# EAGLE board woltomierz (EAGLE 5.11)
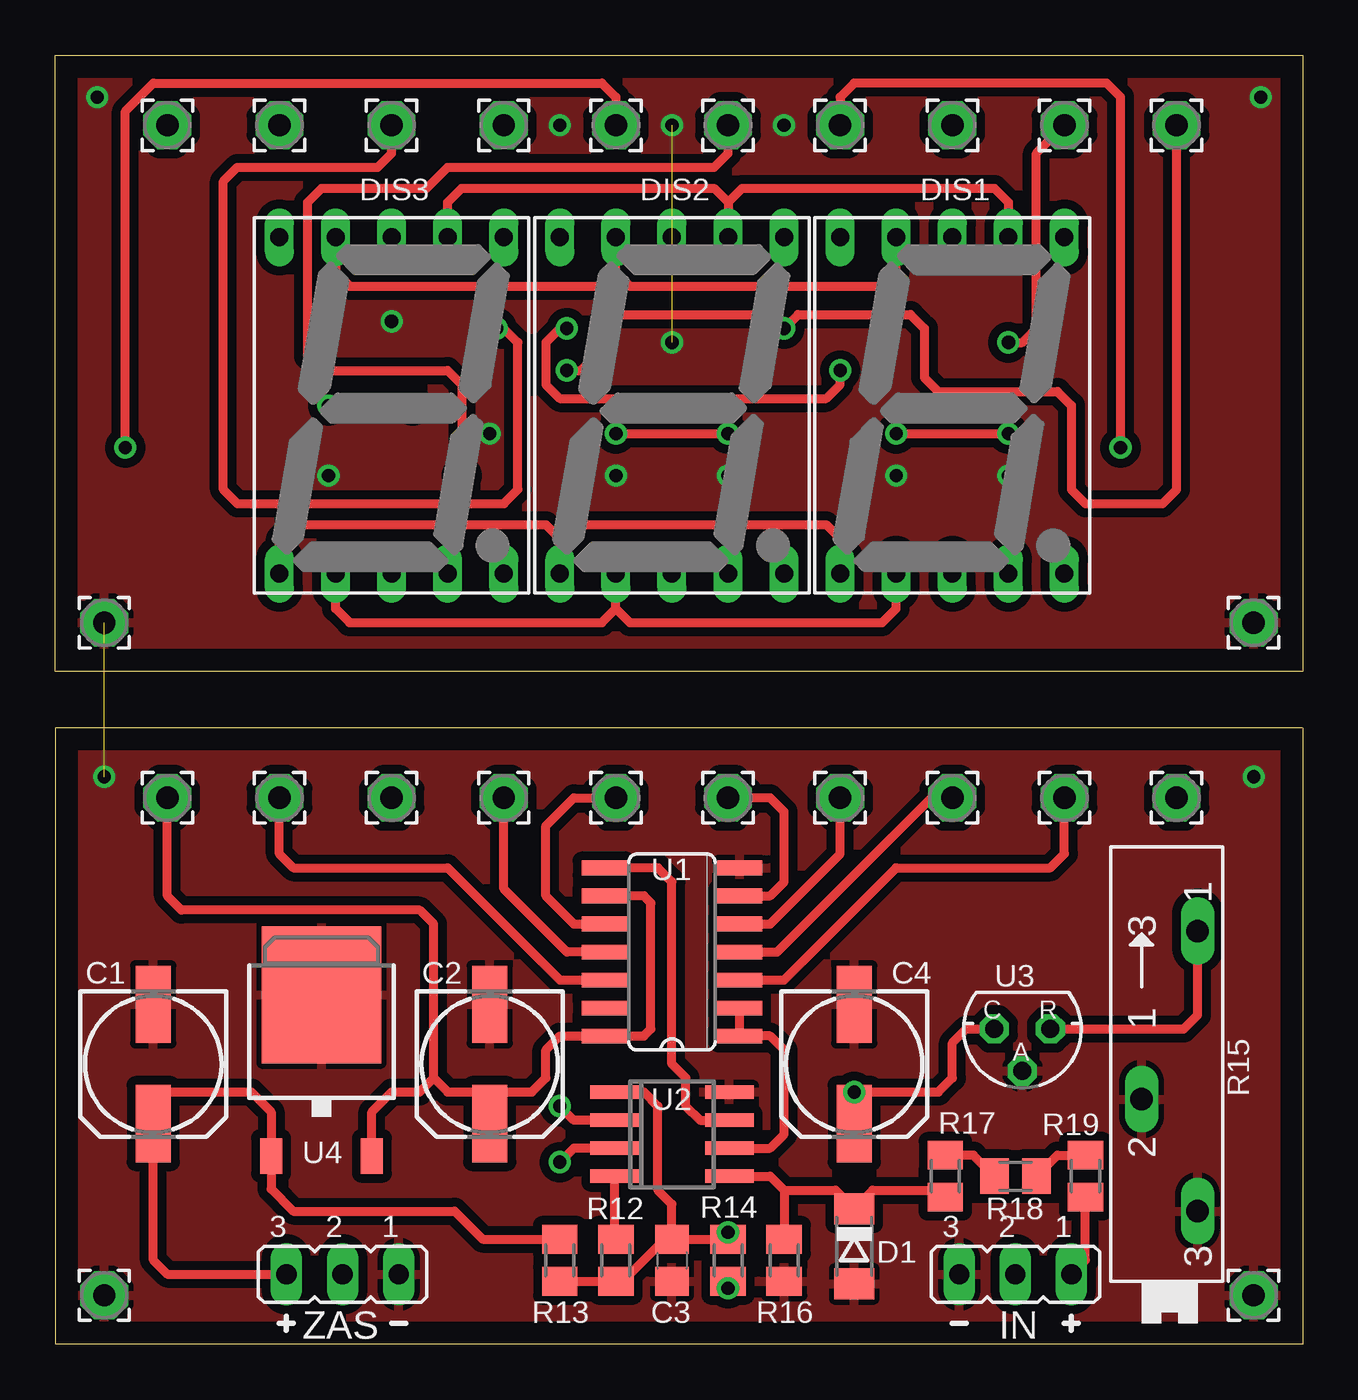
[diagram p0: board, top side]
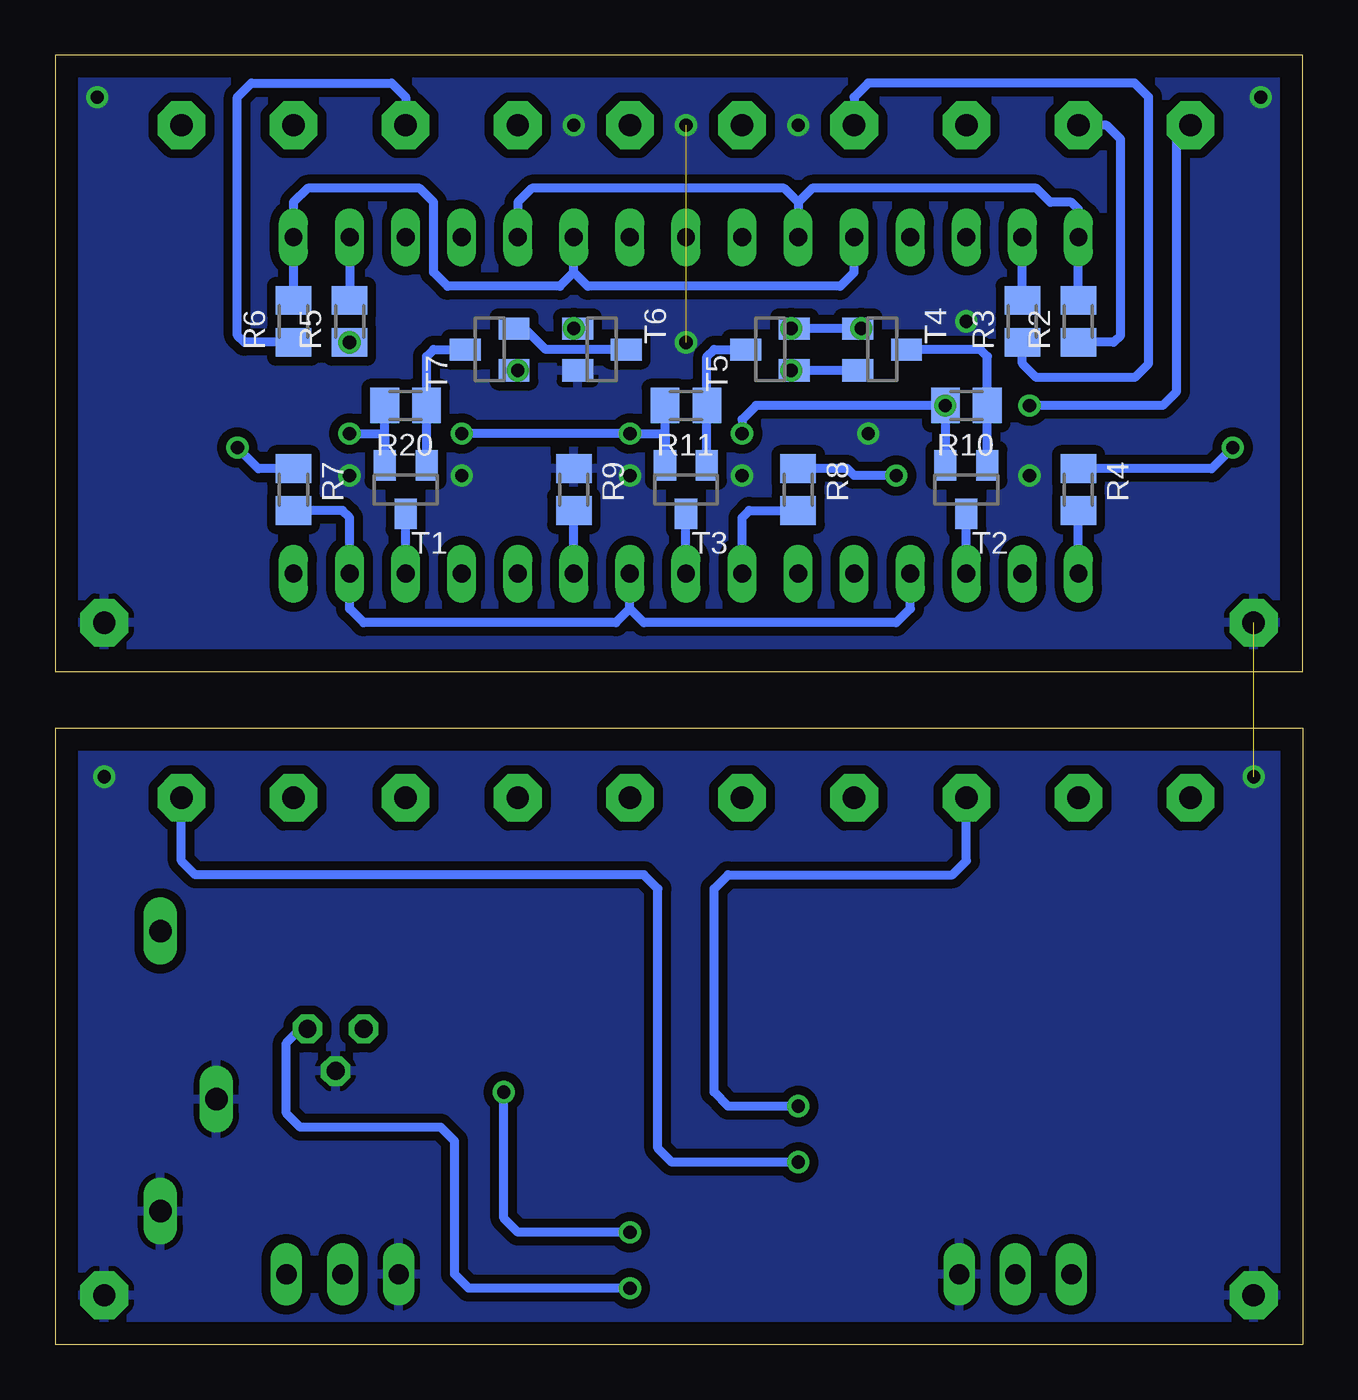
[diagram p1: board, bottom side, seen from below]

Size 56.51 x 58.42 mm. Coordinates in mm from the lower left corner, seen from the top.
Outline: 0,58.42 56.51,58.42 56.51,30.48 0,30.48 0,58.42
Outline: 56.51,27.94 0,27.94 0,0 56.51,0 56.51,27.94
Copper layers (1*16): Top 0.035mm / dielectric 1.5mm / Bottom 0.035mm
Design rules "default": minimum track width 10mil, minimum drill 24mil, track to track 8mil, track to pad 8mil, pad to pad 8mil, via to via 8mil, smd to smd 8mil, copper to edge 40mil, drill to drill 8mil, minimum pad ring 10mil, minimum via ring 8mil, stop-mask expansion 4mil, vias tented up to drill 0mil, thermal gap 10mil

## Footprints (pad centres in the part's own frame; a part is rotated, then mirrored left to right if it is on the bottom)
153CLV-0605 = smd 3.5 x 1.6: + 2.7,0; - -2.7,0
C0805 = smd 1.3 x 1.5: 1 -0.95,0; 2 0.95,0
SOD80C = smd 1.4 x 1.8: A 1.7,0; C -1.7,0
HDSP-M = drill 0.813 long: 1 -5.08,-7.62; 2 -2.54,-7.62; 3 0,-7.62; 4 2.54,-7.62; 5 5.08,-7.62; 6 5.08,7.62; 7 2.54,7.62; 8 0,7.62; 9 -2.54,7.62; 10 -5.08,7.62
JP2 = drill 0.914 long: 1 -2.54,0; 2 0,0; 3 2.54,0
2,15/1,0 = drill 1.016 pad 2.159 octagon: 1 0,0
M0805 = smd 1.3 x 1.6: 1 -0.95,0; 2 0.95,0
SP19L = drill 1.016 long: A 5.715,-1.27; E -6.985,-1.27; S -1.905,1.27
SOT23 = smd 1 x 1.4: 1 -0.95,-1.1; 2 0.95,-1.1; 3 0,1.1
SO14 = smd 0.66 x 2.032: 1 -3.81,-3.073; 2 -2.54,-3.073; 3 -1.27,-3.073; 4 0,-3.073; 5 1.27,-3.073; 6 2.54,-3.073; 7 3.81,-3.073; 8 3.81,3.073; 9 2.54,3.073; 10 1.27,3.073; 11 0,3.073; 12 -1.27,3.073; 13 -2.54,3.073; 14 -3.81,3.073
SO-08 = smd 0.6 x 2.2: 1 -1.905,-2.6; 2 -0.635,-2.6; 3 0.635,-2.6; 4 1.905,-2.6; 5 1.905,2.6; 6 0.635,2.6; 7 -0.635,2.6; 8 -1.905,2.6
TO92-CLP = drill 0.813 octagon: A 0,1.905; C 1.27,0; R -1.27,0
TO252 = smd 1 x 1.6: 1 -2.28,-4.8; 2 2.28,-4.8 | smd 5.4 x 6.2: 3 0,2.5

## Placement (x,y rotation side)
C1  [153CLV-0605]  4.44,12.7 270 top
C2  [153CLV-0605]  19.68,12.7 270 top
C3  [C0805]  27.94,3.81 270 top
C4  [153CLV-0605]  36.2,12.7 270 top
D1  [SOD80C]  36.2,4.44 270 top
DIS1  HD-H103  [HDSP-M]  40.64,42.55 0 top
DIS2  HD-H103  [HDSP-M]  27.94,42.55 0 top
DIS3  HD-H103  [HDSP-M]  15.24,42.55 0 top
IN  [JP2]  43.5,3.17 180 top
PAD1  [2,15/1,0]  45.72,55.24 90 top
PAD2  [2,15/1,0]  45.72,24.77 90 top
PAD3  [2,15/1,0]  40.64,55.24 90 top
PAD4  [2,15/1,0]  40.64,24.77 90 top
PAD5  [2,15/1,0]  35.56,55.24 90 top
PAD6  [2,15/1,0]  35.56,24.77 90 top
PAD7  [2,15/1,0]  30.48,55.24 90 top
PAD8  [2,15/1,0]  30.48,24.77 90 top
PAD9  [2,15/1,0]  25.4,55.24 90 top
PAD10  [2,15/1,0]  25.4,24.77 90 top
PAD11  [2,15/1,0]  20.32,55.24 90 top
PAD12  [2,15/1,0]  20.32,24.77 90 top
PAD13  [2,15/1,0]  10.16,55.24 90 top
PAD14  [2,15/1,0]  10.16,24.77 90 top
PAD15  [2,15/1,0]  15.24,55.24 0 top
PAD16  [2,15/1,0]  15.24,24.77 0 top
PAD17  [2,15/1,0]  50.8,55.24 0 top
PAD18  [2,15/1,0]  50.8,24.77 0 top
PAD19  [2,15/1,0]  54.29,32.7 0 top
PAD20  [2,15/1,0]  2.22,32.7 0 top
PAD21  [2,15/1,0]  2.22,2.22 0 top
PAD22  [2,15/1,0]  54.29,2.22 0 top
PAD23  [2,15/1,0]  5.08,55.24 0 top
PAD24  [2,15/1,0]  5.08,24.77 0 top
R2  [M0805]  10.16,46.36 90 bottom
R3  [M0805]  12.7,46.36 90 bottom
R4  [M0805]  10.16,38.73 270 bottom
R5  [M0805]  43.18,46.36 90 bottom
R6  [M0805]  45.72,46.36 90 bottom
R7  [M0805]  45.72,38.73 270 bottom
R8  [M0805]  22.86,38.73 270 bottom
R9  [M0805]  33.02,38.73 270 bottom
R10  [M0805]  15.24,42.55 180 bottom
R11  [M0805]  27.94,42.55 180 bottom
R12  [M0805]  25.4,3.81 90 top
R13  [M0805]  22.86,3.81 270 top
R14  [M0805]  30.48,3.81 270 top
R15  [SP19L]  50.48,13.02 90 top
R16  [M0805]  33.02,3.81 90 top
R17  [M0805]  40.32,7.62 270 top
R18  [M0805]  43.5,7.62 180 top
R19  [M0805]  46.67,7.62 90 top
R20  [M0805]  40.64,42.55 180 bottom
T1  BSS84  [SOT23]  40.64,38.73 180 bottom
T2  BSS84  [SOT23]  15.24,38.73 180 bottom
T3  BSS84  [SOT23]  27.94,38.73 180 bottom
T4  BSS84  [SOT23]  19.05,45.09 270 bottom
T5  BSS84  [SOT23]  24.13,45.09 90 bottom
T6  BSS84  [SOT23]  31.75,45.09 270 bottom
T7  BSS84  [SOT23]  36.83,45.09 90 bottom
U1  74AC164D  [SO14]  27.94,17.78 90 top
U2  PIC12F675SN  [SO-08]  27.94,9.53 270 top
U3  [TO92-CLP]  43.81,14.29 180 top
U4  7805DT  [TO252]  12.06,13.34 0 top
ZAS  [JP2]  13.02,3.17 180 top

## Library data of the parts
C1-C4 R2-R14 R16-R20 = rcl
D1 = diode
DIS1-DIS3 = display-hp; OC_FARNELL: unknown; OC_NEWARK: unknown
IN ZAS = jumper
PAD1-PAD24 = wirepad
R15 = pot
T1-T7 = transistor-npn
U1 = 74xx-eu
U2 = microchip; MF: MICROCHIP; MPN: PIC12F675-E/SN; OC_FARNELL: 9759026; OC_NEWARK: 92C4341
U3 = v-reg
U4 = linear

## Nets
GND: C1.- C2.- C3.2 C4.- D1.A IN.3 PAD19.1 PAD20.1 PAD21.1 PAD22.1 R9.1 R15.E R15.S R16.1 T6.2 U1.7 U2.8 U3.A U4.3 ZAS.1
N$1: PAD1.1 R5.1
N$2: PAD2.1 U1.3
N$3: PAD3.1 R6.1
N$4: PAD4.1 U1.4
N$5: PAD5.1 R7.1
N$6: PAD6.1 U1.5
N$7: PAD7.1 R8.1
N$8: C1.+ R13.1 U4.1 ZAS.3
N$9: C2.+ PAD24.1 U1.9 U1.14 U4.2
N$10: PAD23.1 R10.2 R11.2 R20.2 T1.2 T2.2 T3.2
N$11: R10.1 T2.1 T4.3
N$12: R12.2 U2.4
N$13: U1.1 U1.2 U2.6
N$14: C3.1 C4.+ R12.1 R13.2 R14.1 U2.1 U3.C
N$15: U1.8 U2.7
N$16: R17.1 R18.2
N$17: R18.1 R19.2
N$18: D1.C R16.2 R17.2 U2.5
N$19: IN.1 R19.1
N$20: R14.2 R15.A U3.R
N$22: R11.1 T3.1 T5.3
N$24: R20.1 T1.1 T7.3
N$25: T6.3 T7.2
N$26: PAD17.1 T4.2 T5.1 T6.1
N$27: DIS1.10 DIS2.10 DIS3.10 R2.2
N$28: PAD16.1 U2.2
N$29: DIS1.9 DIS2.9 DIS3.9 R3.2
N$30: DIS1.1 DIS2.1 DIS3.1 R4.2
N$31: DIS1.7 DIS2.7 DIS3.7 R5.2
N$32: DIS1.6 DIS2.6 DIS3.6 R6.2
N$33: DIS1.4 DIS2.4 DIS3.4 R7.2
N$34: DIS1.2 DIS2.2 DIS3.2 R8.2
N$35: PAD8.1 U1.6
N$36: PAD9.1 R4.1
N$37: PAD10.1 U1.10
N$38: PAD11.1 R3.1
N$39: PAD12.1 U1.11
N$40: PAD13.1 R2.1
N$41: PAD14.1 U1.12
N$42: PAD15.1 T4.1 T5.2 T7.1
N$43: PAD18.1 U2.3
N$48: DIS2.5 R9.2
N$49: DIS1.3 T1.3
N$50: DIS2.3 T3.3
N$51: DIS3.3 T2.3

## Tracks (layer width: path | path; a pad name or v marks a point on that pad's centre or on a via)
GND  (via drill 0.6)  (2 unrouted)
  other vias: 2.22,32.7 54.29,32.7 1.9,56.52 54.61,56.52 2.22,25.72 54.29,25.72 54.29,2.22 2.22,2.22 38.1,39.37 43.18,39.37 30.48,39.37 15.24,46.36 25.4,39.37 12.38,39.37 19.68,41.27 27.94,55.24 33.02,55.24 22.86,55.24 27.94,45.4
  pour Bottom (isolate 0.406): -1.27,59.06 58.42,59.06 58.42,-0.64 -1.27,-0.64
  pour Top (isolate 0.406): -1.27,59.06 58.42,59.06 58.42,-0.64 -1.27,-0.64
N$1  (via drill 0.6)
  Top 0.406: R5.1 43.81,45.4 44.45,46.04 44.45,53.98 PAD1.1
  Bottom 0.406: R5.1
  other vias: 43.18,45.4
N$2
  Top 0.406: U1.3 33.02,16.51 38.1,21.59 45.09,21.59 45.72,22.23 PAD2.1
N$3
  Bottom 0.406: PAD3.1 40.64,56.52 41.27,57.15 47.62,57.15 48.26,56.52 48.26,45.72 47.95,45.41 R6.1
N$4
  Top 0.406: U1.4 32.7,17.78 39.69,24.77 PAD4.1
N$5  (via drill 0.6)
  Top 0.406: PAD5.1 35.56,56.52 36.2,57.15 47.62,57.15 48.26,56.52 v48.26,40.64
  Bottom 0.406: R7.1 47.3,39.69 v48.26,40.64
N$6
  Top 0.406: U1.5 32.38,19.05 35.56,22.23 PAD6.1
N$7  (via drill 0.6)
  Top 0.406: PAD7.1 30.48,53.98 29.84,53.34 17.78,53.34 16.83,52.39 12.06,52.39 11.43,51.75 11.43,44.77 12.06,44.13 17.78,44.13 18.41,43.5 v18.41,39.37
  Bottom 0.406: v18.41,39.37 20.32,39.37 20.64,39.69 R8.1
N$8
  Top 0.406: R13.1 19.36,4.76 18.1,6.03 10.79,6.03 9.78,7.04 U4.1 9.78,10.54 8.89,11.43 4.44,11.43 C1.+ 4.44,3.81 5.08,3.17 ZAS.3
N$9
  Top 0.406: 20.16,9.53 C2.+ 19.68,11.43 | 19.68,11.43 21.59,11.43 22.23,12.07 22.23,13.34 22.86,13.97 U1.14 26.67,13.97 26.99,14.29 26.99,20 26.67,20.32 U1.9 | U4.2 14.35,10.54 15.24,11.43 16.51,11.43 17.14,12.07 | PAD24.1 5.08,20.32 5.71,19.69 16.51,19.69 17.14,19.05 17.14,12.07 | 19.68,11.43 17.78,11.43 17.14,12.07
N$10  (via drill 0.6)
  Top 0.406: v25.4,41.27 v30.48,41.27 | v38.1,41.27 v43.18,41.27 | v12.38,42.55 R10.2
  Bottom 0.406: 41.59,41.27 T1.2 | 41.59,41.27 R20.2 | 28.89,41.27 T3.2 | 28.89,41.27 R11.2 | R10.2 T2.2 | R10.2 | R10.2 24.77,42.55 25.4,41.91 v25.4,41.27 | 28.89,41.27 v30.48,41.27 v38.1,41.27 | v43.18,41.27 41.59,41.27 | R10.2 16.19,41.28 16.19,41.27 R10.2 | PAD23.1 5.71,54.61 5.71,43.18 6.35,42.55 v12.38,42.55
  other vias: 16.19,42.55
N$11
  Bottom 0.406: T2.1 R10.1 14.29,44.77 14.6,45.09 T4.3
N$12
  Top 0.406: U2.4 25.34,4.82 R12.2
N$13
  Top 0.406: U1.2 U1.1 32.38,13.97 33.02,13.34 33.02,9.53 32.38,8.89 U2.6
N$14  (via drill 0.6)
  Top 0.406: U2.1 26.67,11.43 27.3,10.8 27.3,6.99 27.94,6.35 C3.1 | R13.2 R12.1 25.71,3.17 26.03,3.17 27.62,4.76 C3.1 | C3.1 R14.1 v30.48,5.08 | U3.C 41.27,14.29 40.64,13.65 40.64,12.07 40,11.43 v36.2,11.43 C4.+
  Bottom 0.406: v30.48,5.08 35.56,5.08 36.2,5.71 v36.2,11.43
N$15
  Top 0.406: U1.8 27.3,21.59 27.94,20.96 27.94,12.7 28.57,12.07 28.57,10.8 29.21,10.16 U2.7
N$16
  Top 0.406: R17.1 41.6,8.57 R18.2
N$17
  Top 0.406: R19.2 45.4,8.57 R18.1
N$18
  Top 0.406: U2.5 32.38,7.62 33.02,6.99 | 33.02,6.99 R16.2 | 33.02,6.99 35.35,6.99 D1.C | D1.C 36.2,6.35 | R17.2 40.64,6.99 37.03,6.99 D1.C
N$19
  Top 0.406: R19.1 46.67,3.81 IN.1
N$20  (via drill 0.6)
  Top 0.406: U3.R 51.12,14.29 51.75,14.92 R15.A | R14.2 v30.48,2.54
  Bottom 0.406: v30.48,2.54 37.78,2.54 38.42,3.17 38.42,9.21 39.05,9.84 45.4,9.84 46.04,10.48 46.04,13.65 45.4,14.29 U3.R
N$22
  Bottom 0.406: T3.1 R11.1 26.99,44.77 26.67,45.09 T5.3
N$24
  Bottom 0.406: T1.1 R20.1 39.69,44.77 39.37,45.09 T7.3
N$25
  Bottom 0.406: T6.3 34.29,45.09 35.24,46.04 T7.2
N$26  (via drill 0.6)
  Top 0.406: v23.18,44.13 23.81,44.13 24.45,44.77 24.45,46.04 25.08,46.67 32.38,46.67 v33.02,46.04 33.66,46.67 38.73,46.67 39.37,46.04 39.37,43.81 40,43.18 45.4,43.18 46.04,42.55 46.04,38.73 46.67,38.1 50.16,38.1 50.8,38.73 PAD17.1
  Bottom 0.406: T4.2 T5.1 v23.17,44.13 v23.18,44.13 | T6.1 32.7,46.04 v33.02,46.04
N$27
  Bottom 0.406: R2.2 DIS3.10 10.16,51.44 10.48,51.75 11.43,51.75 12.06,52.39 22.23,52.39 22.86,51.75 | 22.86,51.75 DIS2.10 | 22.86,51.75 23.49,52.39 34.92,52.39 35.56,51.75 DIS1.10
N$28  (via drill 0.6)
  Top 0.406: v22.86,10.8 23.49,10.16 U2.2
  Bottom 0.406: PAD16.1 15.24,21.91 15.87,21.27 26.03,21.27 26.67,20.64 26.67,11.43 26.03,10.8 v22.86,10.8
N$29
  Top 0.406: DIS3.9 12.7,48.58 13.33,47.94 24.77,47.94 25.4,48.58 | 25.4,48.58 DIS2.9 | 25.4,48.58 26.03,47.94 37.46,47.94 38.1,48.58 DIS1.9
  Bottom 0.406: R3.2 DIS3.9
N$30
  Top 0.406: DIS3.1 10.16,36.51 10.79,37.15 22.23,37.15 22.86,36.51 | 22.86,36.51 DIS2.1 | 22.86,36.51 23.49,37.15 34.92,37.15 35.56,36.51 DIS1.1
  Bottom 0.406: DIS3.1 R4.2
N$31
  Top 0.406: DIS3.7 17.78,51.75 18.41,52.39 29.84,52.39 30.48,51.75 | 30.48,51.75 DIS2.7 | 30.48,51.75 31.11,52.39 42.54,52.39 43.18,51.75 DIS1.7
  Bottom 0.406: DIS1.7 R5.2
N$32
  Bottom 0.406: R6.2 DIS1.6 45.72,51.75 45.09,52.39 40,52.39 39.37,51.75 39.37,48.58 38.73,47.94 33.66,47.94 33.02,48.58 | DIS3.6 20.32,48.58 20.95,47.94 32.38,47.94 33.02,48.58 | 33.02,48.58 DIS2.6
N$33
  Bottom 0.406: R7.2 43.5,37.79 43.18,37.47 DIS1.4 43.18,33.34 42.54,32.7 31.11,32.7 30.48,33.34 | DIS3.4 17.78,33.34 18.41,32.7 29.84,32.7 30.48,33.34 | 30.48,33.34 DIS2.4
N$34
  Top 0.406: DIS1.2 38.1,33.34 37.46,32.7 26.03,32.7 25.4,33.34 | 25.4,33.34 DIS2.2 | DIS3.2 12.7,33.34 13.33,32.7 24.77,32.7 25.4,33.34
  Bottom 0.406: R8.2 25.08,37.79 25.4,37.47 DIS2.2
N$35
  Top 0.406: U1.6 32.38,20.32 33.02,20.96 33.02,24.13 32.38,24.77 PAD8.1
N$36  (via drill 0.6)
  Top 0.406: PAD9.1 25.4,56.52 24.77,57.15 4.44,57.15 3.17,55.88 v3.17,40.64
  Bottom 0.406: R4.1 4.13,39.69 v3.17,40.64
N$37
  Top 0.406: U1.10 23.49,19.05 22.23,20.32 22.23,23.5 23.49,24.77 PAD10.1
N$38
  Bottom 0.406: R3.1 12.7,44.45 12.06,43.81 7.62,43.81 6.99,44.45 6.99,56.52 7.62,57.15 19.68,57.15 20.32,56.52 PAD11.1
N$39
  Top 0.406: U1.11 23.18,17.78 20.32,20.64 PAD12.1
N$40
  Bottom 0.406: R2.1 8.57,45.41 8.26,45.72 8.26,54.61 8.89,55.24 PAD13.1
N$41
  Top 0.406: U1.12 22.86,16.51 17.78,21.59 10.79,21.59 10.16,22.23 PAD14.1
N$42  (via drill 0.6)
  Top 0.406: v23.18,46.04 22.86,46.04 22.23,45.4 22.23,43.5 22.86,42.86 34.92,42.86 35.56,43.5 v35.56,44.13 | v20,46.04 20.32,46.04 20.95,45.4 20.95,38.73 20.32,38.1 8.26,38.1 7.62,38.73 7.62,52.7 8.26,53.34 14.6,53.34 15.24,53.98 PAD15.1
  Bottom 0.406: v23.18,46.04 v23.17,46.04 T5.2 T4.1 v20,46.04 | v35.56,44.13 35.56,43.97 T7.1
N$43  (via drill 0.6)
  Top 0.406: v22.86,8.25 23.49,8.89 U2.3
  Bottom 0.406: PAD18.1 50.8,21.91 50.16,21.27 29.84,21.27 29.21,20.64 29.21,8.89 28.57,8.25 v22.86,8.25
N$48
  Bottom 0.406: DIS2.5 R9.2
N$49
  Bottom 0.406: DIS1.3 T1.3
N$50
  Bottom 0.406: DIS2.3 T3.3
N$51
  Bottom 0.406: DIS3.3 T2.3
